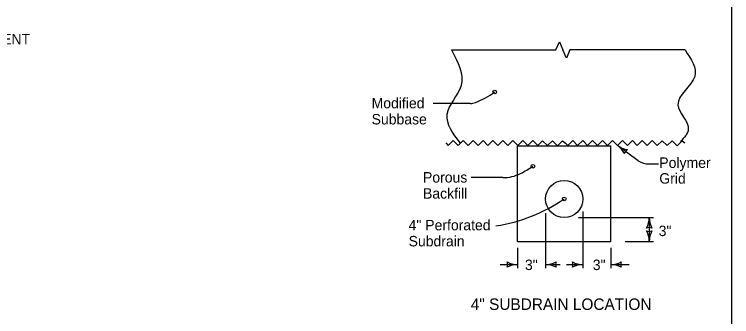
# Model space of a CAD drawing. Extents: x 10130 to 81668, y 5440 to 21644.
# Drawn here: x 15496 to 16868, y 8476 to 9055 of the extents above; entities that cross this region are included whole.
import ezdxf

# ---------------------------------------------------------------- set-up
doc = ezdxf.new("R2010")
doc.units = 0
for name, color, linetype in [('dsnCellElements', 7, 'Continuous'), ('dsnStdBlockModified', 7, 'Continuous'), ('dsnStdBlockNotModified', 7, 'Continuous'), ('dsnStdBorder', 7, 'Continuous'), ('SheetBorder', 7, 'Continuous')]:
    doc.layers.add(name, color=color, linetype=linetype)

msp = doc.modelspace()

# ---------------------------------------------------------------- linework, layer by layer
at = {"layer": 'dsnCellElements'}
for centre in [(16414.4, 8905.9), (16487.3, 8763.8), (16547.3, 8701.1)]:
    msp.add_circle(centre, 3.54, dxfattribs=at)
at = {"layer": 'dsnStdBlockModified'}
for p, q in [((16689, 8773.8), (16649.2, 8803.6)), ((16709.6, 8768.1), (16727.9, 8768.1)), ((16511.6, 8673.7), (16511.6, 8568.9)), ((16582.9, 8677), (16582.9, 8568.9)), ((16574.7, 8665.4), (16718.2, 8665.4)), ((16709.9, 8665.4), (16709.9, 8619.9)), ((16663.8, 8619.9), (16718.2, 8619.9)), ((16458.2, 8607.5), (16458.2, 8568.9)), ((16636.4, 8607.5), (16636.4, 8568.9)), ((16424.8, 8575.5), (16458.2, 8575.5)), ((16511.6, 8575.5), (16539.5, 8575.5)), ((16551.8, 8575.5), (16582.9, 8575.5)), ((16636.4, 8575.5), (16671.5, 8575.5))]:
    msp.add_line(p, q, dxfattribs=at)
msp.add_arc((16709.6, 8807.7), 39.6, 238.7046, 270, dxfattribs=at)
at = {"layer": 'dsnStdBlockNotModified'}
for centre, radius, start, end in [((16623.8, 8769.5), 42.5, 25.1788, 53.2513), ((16674.6, 8837.6), 42.5, 233.2513, 261.3238), ((16677.7, 8782.3), 16.4, 125.5179, 160.9846)]:
    msp.add_arc(centre, radius, start, end, dxfattribs=at)
at = {"layer": 'dsnStdBorder'}
for p, q in [((16367.9, 8884), (16296.6, 8884)), ((16458.2, 8619.5), (16458.2, 8802.9)), ((16458.2, 8802.9), (16636.4, 8802.9)), ((16469.9, 8802.9), (16636.4, 8802.9)), ((16636.4, 8619.5), (16636.4, 8802.9)), ((16430, 8741.9), (16369.5, 8741.9)), ((16458.2, 8619.5), (16636.4, 8619.5))]:
    msp.add_line(p, q, dxfattribs=at)
for points in [[(16331.4, 8986.3), (16531.2, 8986.3), (16538, 9002.1), (16544.8, 8986.3)], [(16778.4, 8986.3), (16558.3, 8986.3), (16551.6, 8970.5), (16544.8, 8986.3)], [(16320.7, 8808.5), (16325.4, 8803.7), (16335, 8813.2), (16344.4, 8803.6), (16354, 8813.1), (16363.5, 8803.6), (16373, 8813.1), (16382.4, 8803.5), (16392, 8813), (16401.5, 8803.5), (16411, 8813), (16420.5, 8803.4), (16430, 8812.9), (16439.5, 8803.4), (16449, 8812.9), (16458.5, 8803.3), (16468, 8812.8), (16477.5, 8803.3), (16487, 8812.8), (16496.5, 8803.2), (16506, 8812.7), (16515.5, 8803.2), (16525, 8812.7), (16534.5, 8803.1), (16544, 8812.6), (16549.8, 8808)], [(16549.3, 8808.5), (16554, 8803.7), (16563.5, 8813.2), (16573, 8803.6), (16582.6, 8813.1), (16592, 8803.6), (16601.5, 8813.1), (16611, 8803.5), (16620.6, 8813), (16630, 8803.5), (16639.6, 8813), (16649.1, 8803.4), (16658.6, 8812.9), (16668, 8803.4), (16677.6, 8812.9), (16687.1, 8803.3), (16696.6, 8812.8), (16706.1, 8803.3), (16715.6, 8812.8), (16725.1, 8803.2), (16734.6, 8812.7), (16744.1, 8803.2), (16753.6, 8812.7), (16763.1, 8803.1), (16772.6, 8812.6), (16777.8, 8808.5)]]:
    msp.add_lwpolyline(points, dxfattribs=at)
msp.add_circle((16547.3, 8701.1), 35.6, dxfattribs=at)
for centre, radius, start, end in [((16300.9, 9071.6), 200.9, 292.4048, 304.4007), ((16367.9, 8909), 25, 270, 292.4048), ((16373.8, 8929.5), 200.9, 296.5518, 304.4007), ((16430, 8816.9), 75, 270, 296.5518), ((16369.6, 8960.5), 314.4, 278.602, 304.4007), ((16667.4, 8665.4), 42.5, 331.9275, 360), ((16752.4, 8665.4), 42.5, 180, 208.0725), ((16709.9, 8629.8), 16.4, 72.2666, 107.7334), ((16709.9, 8655.5), 16.4, 252.2666, 287.7333), ((16667.4, 8619.9), 42.5, 360, 28.0725), ((16752.4, 8619.9), 42.5, 151.9275, 180), ((16422.5, 8575.5), 16.4, 342.2666, 17.7333), ((16458.2, 8618), 42.5, 241.9275, 270), ((16458.2, 8533), 42.5, 90, 118.0725), ((16511.6, 8618), 42.5, 270, 298.0725), ((16511.6, 8618), 42.5, 270, 298.0725), ((16511.6, 8533), 42.5, 61.9275, 90), ((16511.6, 8533), 42.5, 61.9275, 90), ((16547.3, 8575.5), 16.4, 162.2666, 197.7334), ((16547.3, 8575.5), 16.4, 162.2666, 197.7334), ((16547.3, 8575.5), 16.4, 342.2666, 17.7333), ((16582.9, 8618), 42.5, 241.9275, 270), ((16547.3, 8575.5), 16.4, 342.2666, 17.7333), ((16582.9, 8618), 42.5, 241.9275, 270), ((16582.9, 8533), 42.5, 90, 118.0725), ((16582.9, 8533), 42.5, 90, 118.0725), ((16636.4, 8618), 42.5, 270, 298.0725), ((16636.4, 8533), 42.5, 61.9275, 90), ((16672, 8575.5), 16.4, 162.2666, 197.7334)]:
    msp.add_arc(centre, radius, start, end, dxfattribs=at)
for points in [[(16331.4, 8986.3), (16349.9, 8918.5), (16322.8, 8862.8), (16347.5, 8808.5)], [(16778.4, 8986.3), (16796.9, 8935.8), (16764.8, 8881.4), (16784.6, 8834.4), (16769.8, 8810.9)]]:
    msp.add_spline(points, degree=3, dxfattribs=at)
at = {"layer": 'SheetBorder'}
msp.add_lwpolyline([(13732.5, 9944), (16867.5, 9944), (16867.5, 7924), (13732.5, 7924)], close=True, dxfattribs=at)

# ---------------------------------------------------------------- texts
at = {"layer": 'dsnStdBlockModified'}
for s, p in [('SECTION THRU CENTERLINE - SOUTH APPROACH PAVEMENT', (14718.8, 8997)), ('Modified', (16178.9, 8874.7)), ('Subbase', (16178.9, 8843.8)), ('Polymer ', (16729.2, 8760.5)), ('Porous', (16277.2, 8732.5)), ('Grid', (16729.2, 8730.5)), ('Backfill', (16277.2, 8701.7)), ('4" Perforated ', (16249.7, 8641.1)), ('3"', (16728, 8630)), ('Subdrain', (16249.7, 8610.3)), ('3"', (16472.2, 8565)), ('3"', (16601.9, 8565))]:
    msp.add_text(s, height=20, dxfattribs=at).set_placement(p)
at = {"layer": 'dsnStdBorder'}
msp.add_text('4" SUBDRAIN LOCATION', height=22, dxfattribs=at).set_placement((16368.6, 8488.6))

doc.saveas('drawing.dxf')
